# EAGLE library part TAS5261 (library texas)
315-W Mono BTL Digital Amplifier Power Stage Source: http://focus.ti.com/lit/ds/symlink/tas5261.pdf
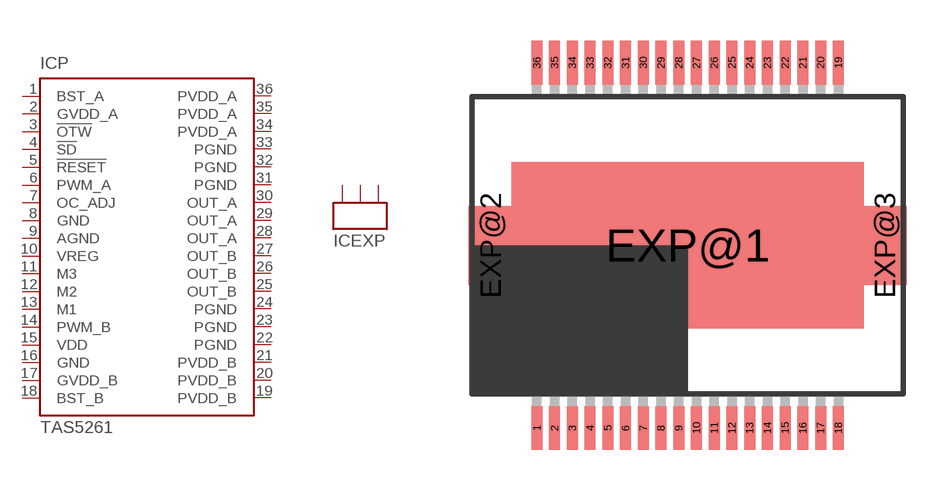
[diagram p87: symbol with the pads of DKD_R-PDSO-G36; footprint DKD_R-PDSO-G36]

Designator prefix IC; gates P=TAS5261 EXP=EXP-3

## TAS5261 (MF: TEXAS INSTRUMENT CONNECTORS; MPN: TAS5261DKD; OC_FARNELL: 1564920; OC_NEWARK: 18M3142)  [DKD_R-PDSO-G36]
1  P:BST_A  in
2  P:GVDD_A  in
3  P:!OTW  in
4  P:!SD  in
5  P:!RESET  in
6  P:PWM_A  in
7  P:OC_ADJ  in
8  P:GND  in
9  P:AGND  in
10  P:VREG  in
11  P:M3  in
12  P:M2  in
13  P:M1  in
14  P:PWM_B  in
15  P:VDD  in
16  P:GND  in
17  P:GVDD_B  in
18  P:BST_B  in
19  P:PVDD_B  in
20  P:PVDD_B  in
21  P:PVDD_B  in
22  P:PGND  in
23  P:PGND  in
24  P:PGND  in
25  P:OUT_B  in
26  P:OUT_B  in
27  P:OUT_B  in
28  P:OUT_A  in
29  P:OUT_A  in
30  P:OUT_A  in
31  P:PGND  in
32  P:PGND  in
33  P:PGND  in
34  P:PVDD_A  in
35  P:PVDD_A  in
36  P:PVDD_A  in
EXP@1  EXP:EXP  in
EXP@2  EXP:EXP  in
EXP@3  EXP:EXP  in

## Footprint DKD_R-PDSO-G36 (pad centres in mm)
Thermally-enhanced 36-pin PSOP3 PowerPAD(TM) package Source: http://focus.ti.com/lit/ds/symlink/tas5261.pdf
smd 0.4 x 1.6: 1 -5.525,-6.7; 2 -4.875,-6.7; 3 -4.225,-6.7; 4 -3.575,-6.7; 5 -2.925,-6.7; 6 -2.275,-6.7; 7 -1.625,-6.7; 8 -0.975,-6.7; 9 -0.325,-6.7; 10 0.325,-6.7; 11 0.975,-6.7; 12 1.625,-6.7; 13 2.275,-6.7; 14 2.925,-6.7; 15 3.575,-6.7; 16 4.225,-6.7; 17 4.875,-6.7; 18 5.525,-6.7; 19 5.525,6.7; 20 4.875,6.7; 21 4.225,6.7; 22 3.575,6.7; 23 2.925,6.7; 24 2.275,6.7; 25 1.625,6.7; 26 0.975,6.7; 27 0.325,6.7; 28 -0.325,6.7; 29 -0.975,6.7; 30 -1.625,6.7; 31 -2.275,6.7; 32 -2.925,6.7; 33 -3.575,6.7; 34 -4.225,6.7; 35 -4.875,6.7; 36 -5.525,6.7
smd 12.9 x 6.1: EXP@1 0,0
smd 1.6 x 2.9: EXP@2 -7.225,0; EXP@3 7.225,0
